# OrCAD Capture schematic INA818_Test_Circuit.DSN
size A; title: INA188 Precision, Zero-Drift, Rail-to-Rail Out, High-Voltage; rev: 1.2; note: Datasheet: SBOS894A EVM: N/A
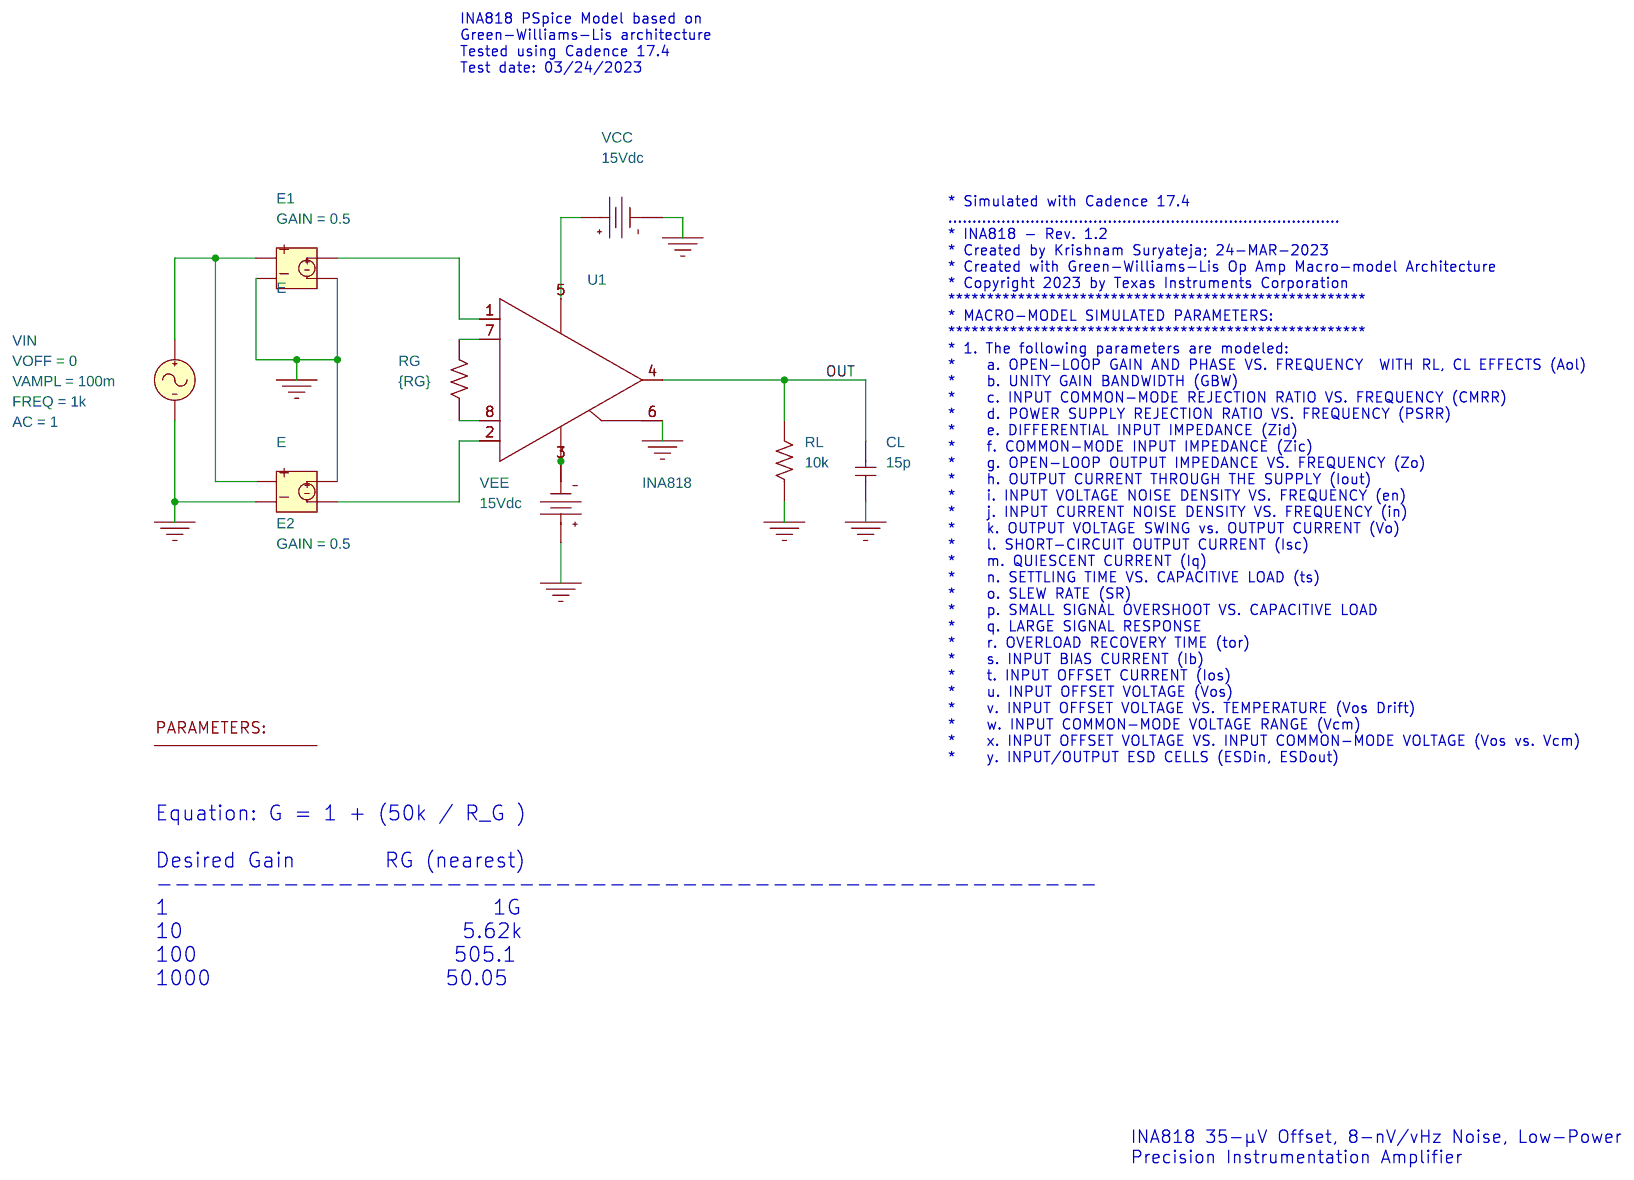
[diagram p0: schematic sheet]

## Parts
1  PARAM
CL  15p  [RAD/CK05]
E1  E
E2  E
RG  {RG}  [AX/RC05]
RL  10k  [AX/RC05]
U1  INA818
VCC  VDC
VEE  VDC
VIN  VSIN

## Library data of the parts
1 = PARAM: RG: 1G
CL = C
E1 E2 = E: GAIN: 0.5
RG RL = R
U1 = INA818
VCC VEE = VDC: DC: 15Vdc
VIN = VSIN: AC: 1; FREQ: 1k; VAMPL: 100m; VOFF: 0

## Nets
0: CL.1 E1.2 E1.4 E2.2 E2.3 RL.1 U1.6(REF) VCC.1(-) VEE.0(+) VIN.2(-)
OUT: CL.2 RL.2 U1.4(OUT)
N1652038: U1.5(V+) VCC.0(+)
N1652092: E1.1 E2.1 VIN.1(+)
N1652110: E1.3 U1.1(+)
N1652206: RG.2 U1.7(RG+)
N1652316: RG.1 U1.8(RG-)
N1652368: E2.4 U1.2(-)
N1652446: U1.3(V-) VEE.1(-)

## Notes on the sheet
- INA818 PSpice Model based on
  Green-Williams-Lis architecture
  Tested using Cadence 17.4
  Test date: 03/24/2023
- * Simulated with Cadence 17.4
  .................................................................................
  * INA818 - Rev. 1.2
  * Created by Krishnam Suryateja; 24-MAR-2023
  * Created with Green-Williams-Lis Op Amp Macro-model Architecture
  * Copyright 2023 by Texas Instruments Corporation
  ******************************************************
  * MACRO-MODEL SIMULATED PARAMETERS:
  ******************************************************
  * 1. The following parameters are modeled:
  *    a. OPEN-LOOP GAIN AND PHASE VS. FREQUENCY  WITH RL, CL EFFECTS (Aol)
  *    b. UNITY GAIN BANDWIDTH (GBW)
  *    c. INPUT COMMON-MODE REJECTION RATIO VS. FREQUENCY (CMRR)
  *    d. POWER SUPPLY REJECTION RATIO VS. FREQUENCY (PSRR)
  *    e. DIFFERENTIAL INPUT IMPEDANCE (Zid)
  *    f. COMMON-MODE INPUT IMPEDANCE (Zic)
  *    g. OPEN-LOOP OUTPUT IMPEDANCE VS. FREQUENCY (Zo)
  *    h. OUTPUT CURRENT THROUGH THE SUPPLY (Iout)
  *    i. INPUT VOLTAGE NOISE DENSITY VS. FREQUENCY (en)
  *    j. INPUT CURRENT NOISE DENSITY VS. FREQUENCY (in)
  *    k. OUTPUT VOLTAGE SWING vs. OUTPUT CURRENT (Vo)
  *    l. SHORT-CIRCUIT OUTPUT CURRENT (Isc)
  *    m. QUIESCENT CURRENT (Iq)
  *    n. SETTLING TIME VS. CAPACITIVE LOAD (ts)
  *    o. SLEW RATE (SR)
  *    p. SMALL SIGNAL OVERSHOOT VS. CAPACITIVE LOAD
  *    q. LARGE SIGNAL RESPONSE
  *    r. OVERLOAD RECOVERY TIME (tor)
  *    s. INPUT BIAS CURRENT (Ib)
  *    t. INPUT OFFSET CURRENT (Ios)
  *    u. INPUT OFFSET VOLTAGE (Vos)
  *    v. INPUT OFFSET VOLTAGE VS. TEMPERATURE (Vos Drift)
  *    w. INPUT COMMON-MODE VOLTAGE RANGE (Vcm)
  *    x. INPUT OFFSET VOLTAGE VS. INPUT COMMON-MODE VOLTAGE (Vos vs. Vcm)
  *    y. INPUT/OUTPUT ESD CELLS (ESDin, ESDout)
- Equation: G = 1 + (50k / R_G )
  Desired Gain        RG (nearest)
  ----------------------------------------------------
  1                             1G
  10                         5.62k
  100                       505.1
  1000                     50.05
- INA818 35-µV Offset, 8-nV/vHz Noise, Low-Power
- Precision Instrumentation Amplifier
